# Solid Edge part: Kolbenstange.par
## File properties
Username: bmolnar
Dokumentum tartalom típus: 0
Author: bmolnar
Last saved by: bmolnar
Revision: 92
Sűrűség: 0,000 kg/m^3
Pontosság: 0,990
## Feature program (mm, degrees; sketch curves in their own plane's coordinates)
base feature "unnamed BaseFeature 1"
thread "unnamed Thread 1"
sketch for "Kihúzás_1" plane through (26.75, 0, 0) normal (1, 0, 0) x-axis (0, -1, 0)
  circle centre (0, 0) radius 31.5
extrude "Kihúzás_1" add finite 10.75 along +normal
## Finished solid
Body 1: solid body, 14 faces, 20 edges, 8 vertices.
  Faces by surface: plane 7, cylinder 4, cone 2, torus 1
  Edges by curve: circle 10, line 6, ellipse 2, intersection 2
Bounding box of the edges (mm; curved faces can reach further): 192.500 x 63.000 x 63.000, from (-155, -31.5, -31.5) to (37.5, 31.5, 31.5).
Cylindrical faces by radius (mm): R4.188 x2, R8 x1, R31.5 x1
Conical faces (half-angle, radius in mm at the cone's reference point): 45 deg R4.538 x1, 59 deg R2.094 x1
Toroidal faces (ring radius, tube radius in mm): R6.3 r1.7 x1
Planar faces by outward normal: +x 1, +z 1, -x 2, -z 1, oblique 2
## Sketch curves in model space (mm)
circle centre (26.75, 0, 0) radius 31.5
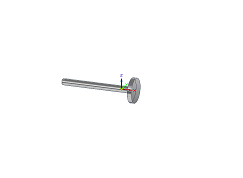
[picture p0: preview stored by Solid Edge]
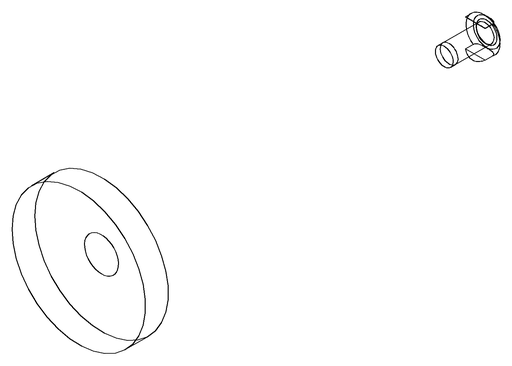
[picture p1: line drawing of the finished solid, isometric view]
